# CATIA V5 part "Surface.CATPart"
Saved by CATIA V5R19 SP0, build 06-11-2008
Part number: Surface
Bounding box of the stored display mesh (mm): x -2.399 to 2.399, y -10 to 19.596, z -24.164 to 7
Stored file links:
  D:\VKW\Work\Process_And_Tools\Courseware_Development\Tangix_Certification_Project\SUR_Associate\Preparation_Kit\Data\Surface.CATPart
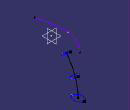
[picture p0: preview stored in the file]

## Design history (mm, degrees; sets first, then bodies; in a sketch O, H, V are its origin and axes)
Set1 "INPUT"
  Sketch1 "Sketch.1" on yz-plane, origin (0, 0, 0), H (0, 1, 0), V (0, 0, 1)
    spline S1 through (-10, 4.5) (-1.3956, 6.2) (10, 7)
    construction line L1 (10, 0) -> (10, 8.9606)
    point P1 (10, 0)
    arc A1 centre (10, 0) radius 7 from (17, 0) to (10, 7) ccw
    point P3 (10, 7)
    point P4 (17, 0)
    axis line L2 (-8.2149, 0) -> (10.5666, 0)
    point P5 (-8.2149, 0)
    point P7 (-10, 4.5)
    point P8 (10, 7)
    point P9 (-1.3956, 6.2)
    distance V P7 = 10
    distance P8 V = 10
    distance H P8 = 7
    distance H P7 = 4.5
    distance P9 H = 6.2
    coincidence: P1 H, P8 L1, P8 P3, P4 H, P5 H
    vertical: L1 V
    tangency: S1 A1
    horizontal: L2 H
  Sketch2 on yz-plane, origin (0, 0, 0), H (0, 1, 0), V (0, 0, 1)
    spline S1 through (9, -4.2) (13, -11) (16, -24)
    point P1 (9, -4.2)
    point P2 (13, -11)
    point P3 (16, -24)
    distance V P1 = 9
    distance P1 H = 4.2
    distance P2 V = 13
    distance P2 H = 11
    distance P3 V = 16
    distance P3 H = 24
  Sketch3 on Plane3, origin (0, 5.5874, -6.7459), H (1, 0, 0), V (0, 0.8015, 0.598)
    point P1 (0, 4.2576)
    ellipse A1 centre (0, 4.2576) semi-axes 3, 2 rotation 270
    point P2 (0, 1.2576)
    reference projected point E1 (0, 4.2576) from Sketch2.P1
    coincidence: P1 V, P2 V, A1 P2, P1 E1
  Sketch4 on Plane2, origin (0, 6.9971, -16.0297), H (1, 0, 0), V (0, 0.9434, 0.3316)
    circle A1 centre (0, 7.4423) radius 2
    radius A1 = 2
  Sketch5 on Plane1, origin (0, 3.3661, -24.5748), H (1, 0, 0), V (0, 0.999, 0.0455)
    point P1 (0, 12.6469)
    ellipse A1 centre (0, 12.6469) semi-axes 3.6, 2.4 rotation 90
    point P2 (0, 9.0469)
    reference projected point E1 (0, 12.6469) from Sketch2.P3
    coincidence: P1 V, P2 V, A1 P2, P1 E1
  Sketch6 "Sketch.6" on Plane4, origin (0, 23, 0), H (-1, 0, 0), V (0, 0, 1)
    construction line L1 (0, 0) -> (-0.6543, 7.4785)
    axis line L2 (0, 0) -> (0.6197, 7.0837)
    line L3 (-0.175, 2) -> (0.175, 2)
    line L4 (0.175, 2) -> (0.3994, 4.5651)
    line L5 (0.0009, 5) -> (-0.0009, 5)
    line L6 (-0.3994, 4.5651) -> (-0.175, 2)
    arc A1 centre (0.0009, 4.6) radius 0.4 from (0.0009, 5) to (0.3994, 4.5651) cw
    arc A2 centre (-0.0009, 4.6) radius 0.4 from (-0.3994, 4.5651) to (-0.0009, 5) cw
    angle V L2 = 5
    angle L1 V = 5
    distance L5 L3 = 3
    distance L3 H = 2
    radius A1 = 0.4
    radius A2 = 0.4
    horizontal: L3 H, L5 H
    coincidence: L6 L1, L4 L2
    tangency: A1 L5, A1 L4, A2 L6, A2 L5
  Near1 "Point.3": ReferenceElement Sketch1, MultiElement Intersect1
  Near2 "Point.4": ReferenceElement Sketch1, MultiElement Intersect2
  Near3 "Point.5": ReferenceElement Sketch1, MultiElement Intersect3
  Line1: type PtDir, Direction zx-plane, Start 0, End 20, RefPoint {point type Coord, X 0, Y 0, Z 0}
Set2 "Ref"
  Plane1: type Normal, Curve Sketch2, RefPoint Sketch2.P3
  Plane2: type Normal, Curve Sketch2
  Plane3: type Normal, Curve Sketch2, RefPoint Sketch2.P1
  Plane4: type Offset, Offset 23, RefPlane zx-plane
  Intersect1: ToIntersect1 yz-plane, ToIntersect2 Sketch3
  Intersect2: ToIntersect1 yz-plane, ToIntersect2 Sketch4
  Intersect3: ToIntersect1 yz-plane, ToIntersect2 Sketch5
Body1 (main body)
